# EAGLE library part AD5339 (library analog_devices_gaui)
16-Bit DAC with Serial Data Interface
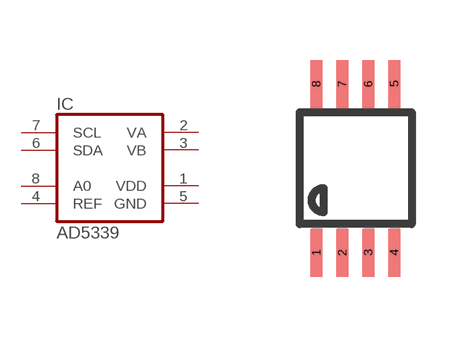
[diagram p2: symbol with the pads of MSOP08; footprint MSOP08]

Designator prefix IC

## AD5339  [MSOP08]
1  VDD  pwr
2  VA  out
3  VB  out
4  REF  in
5  GND  pwr
6  SDA  in
7  SCL  in
8  A0  in

## Footprint MSOP08 (pad centres in mm)
Mini Small Outline Package Grid 0.5mm
smd 0.3 x 1.2: 1 -0.976,-2.113; 2 -0.326,-2.113; 3 0.324,-2.113; 4 0.974,-2.113; 5 0.974,2.112; 6 0.324,2.112; 7 -0.326,2.112; 8 -0.976,2.112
